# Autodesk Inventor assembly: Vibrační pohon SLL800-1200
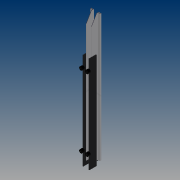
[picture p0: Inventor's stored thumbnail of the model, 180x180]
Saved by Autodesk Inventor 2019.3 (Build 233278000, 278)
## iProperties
Created: 2019-02
Part Number: Vibrační pohon SLL800-1200
Material: Všeobecné
Document SubType Name: Assembly
Designer: B-hon
Author: B-hon
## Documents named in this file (6)
- C:\Users\B-hon\OneDrive\Plocha\Bakalářka22\Vibrační pohon2\Vibrační pohon SLL800-1200.iam
- C:\Users\B-hon\OneDrive\Plocha\Bakalářka22\Vibrační pohon2\Lišta upevňovací-L.ipt
- C:\Users\B-hon\OneDrive\Plocha\Bakalářka22\Vibrační pohon2\Lišta upevňovací-P.ipt
- C:\Users\B-hon\OneDrive\Plocha\Bakalářka22\Vibrační pohon2\Boční plech.ipt
- C:\Users\B-hon\OneDrive\Plocha\Bakalářka22\Vibrační pohon2\Zadní plech.ipt
- C:\Users\B-hon\OneDrive\Plocha\Bakalářka22\Vibrační pohon2\Silentblok.ipt
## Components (9 placed, 5 different names)
1. Lišta upevňovací-L:1 — Stejný směr:1, Stejný směr:2, Proti sobě:1, Stejný směr:3, Proti sobě:3, Proti sobě:4
2. Lišta upevňovací-P:1 — Stejný směr:1, Stejný směr:2, Proti sobě:1, Stejný směr:5, Proti sobě:11, Stejný směr:6
3. Zadní plech:1 — Proti sobě:4, Stejný směr:5, Stejný směr:6
4. Boční plech:1 — Stejný směr:3, Proti sobě:3, Proti sobě:6, Proti sobě:7, Proti sobě:9, Proti sobě:11
5. Boční plech:2 — Proti sobě:5, Proti sobě:8, Proti sobě:10
6. Silentblok:1 — Proti sobě:5, Proti sobě:8, Proti sobě:10
7. Silentblok:2 — Proti sobě:6, Proti sobě:7, Proti sobě:9
8. Silentblok:3
9. Silentblok:4
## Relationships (15: Mate 10, Flush 5)
- Stejný směr:1 [Flush]: Lišta upevňovací-L:1 ↔ Lišta upevňovací-P:1
- Stejný směr:2 [Flush]: Lišta upevňovací-L:1 ↔ Lišta upevňovací-P:1
- Proti sobě:1 [Mate]: Lišta upevňovací-L:1 ↔ Lišta upevňovací-P:1
- Stejný směr:3 [Flush]: Lišta upevňovací-L:1 ↔ Boční plech:1
- Proti sobě:3 [Mate]: Lišta upevňovací-L:1 ↔ Boční plech:1
- Proti sobě:4 [Mate]: Lišta upevňovací-L:1 ↔ Zadní plech:1
- Stejný směr:5 [Flush]: Lišta upevňovací-P:1 ↔ Zadní plech:1
- Proti sobě:5 [Mate]: Boční plech:2 ↔ Silentblok:1
- Proti sobě:6 [Mate]: Boční plech:1 ↔ Silentblok:2
- Proti sobě:7 [Mate]: Boční plech:1 ↔ Silentblok:2
- Proti sobě:8 [Mate]: Boční plech:2 ↔ Silentblok:1
- Proti sobě:9 [Mate]: Boční plech:1 ↔ Silentblok:2
- Proti sobě:10 [Mate]: Boční plech:2 ↔ Silentblok:1
- Proti sobě:11 [Mate]: Lišta upevňovací-P:1 ↔ Boční plech:1
- Stejný směr:6 [Flush]: Lišta upevňovací-P:1 ↔ Zadní plech:1
